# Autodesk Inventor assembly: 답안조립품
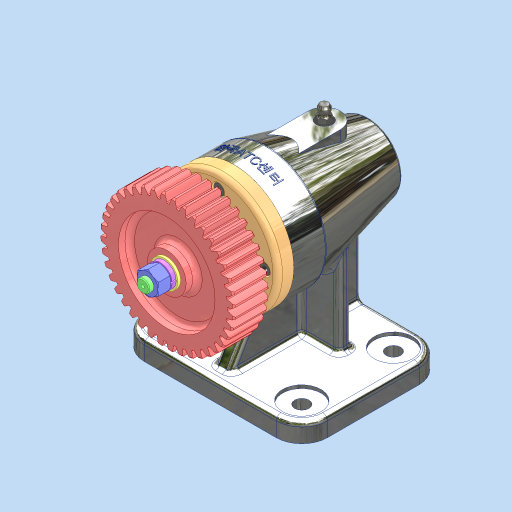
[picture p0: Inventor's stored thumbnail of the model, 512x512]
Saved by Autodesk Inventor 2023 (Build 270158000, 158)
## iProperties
Created: 2024-12
Part Number: 답안조립품
Document SubType Name: Assembly
Designer: asung
Author: asung
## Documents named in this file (15)
- C:\Users\asung\Desktop\741204v1011\답안조립품.iam
- C:\Users\asung\Desktop\741204v1011\본체.ipt
- C:\Users\asung\Documents\Inventor\그리스 니플 M6x0.75.ipt
- C:\Users\asung\Desktop\741204v1011\가져온 구성요소\스퍼기어\스퍼기어.ipt
- C:\Users\asung\Desktop\741204v1011\가져온 구성요소\스프링 와셔 M8\스프링 와셔 M8.ipt
- C:\Users\asung\Desktop\741204v1011\가져온 구성요소\실링\실링.ipt
- C:\Users\asung\Desktop\741204v1011\가져온 구성요소\앵귤러 볼 베어링 7003A\앵귤러 볼 베어링 7003A.ipt
- C:\Users\asung\Desktop\741204v1011\가져온 구성요소\앵귤러 볼 제어링 7204A\앵귤러 볼 제어링 7204A.ipt
- C:\Users\asung\Desktop\741204v1011\가져온 구성요소\오일 실 20 32 8\오일 실 20 32 8.ipt
- C:\Users\asung\Desktop\741204v1011\가져온 구성요소\육각 너트 M8\육각 너트 M8.ipt
- C:\Users\asung\Desktop\741204v1011\가져온 구성요소\육각 소켓 머리 볼트 M4x10\육각 소켓 머리 볼트 M4x10.ipt
- C:\Users\asung\Desktop\741204v1011\가져온 구성요소\축\축.ipt
- C:\Users\asung\Desktop\741204v1011\가져온 구성요소\커버\커버.ipt
- C:\Users\asung\Desktop\741204v1011\가져온 구성요소\평와셔 M8\평와셔 M8.ipt
- C:\Users\asung\Desktop\741204v1011\가져온 구성요소\평행 키 4x4x14\평행 키 4x4x14.ipt
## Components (1 placed, 1 different names)
1. 그리스 니플 M6x0.75:1
